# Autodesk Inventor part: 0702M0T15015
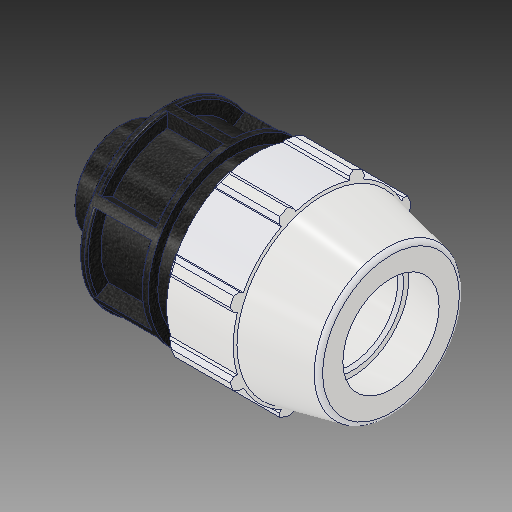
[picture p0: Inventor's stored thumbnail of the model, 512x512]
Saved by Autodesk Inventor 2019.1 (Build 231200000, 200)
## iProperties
Created: 2017-02
Part Number: 0702M0T15015
Material: PVC-Piping
Description: PLASSON MALE ADAPTOR 1 1/2'' - 1 1/2''M
Document SubType Name: Modeling
Designer: KIM
Mass: 92.6774 g
Surface Area: 199.44 cm^2
Volume: 66.1981 cm^3
Density: 1.4 g/cm^3
Appearance: PTFE
Author: KIM
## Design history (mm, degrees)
derived "0702M0T.ipt"
feature "Solid1::0702M0T.ipt"
tag "TaggingFeature1"
body "Solid1"
other parameters: "d2" = 48.1, "d4" = 19.26771, "d5" = 33.7185, "d7" = 96.012, "d8" = 72.009, "d9" = 19.26771, "d11" = 3.85354, "d12" = 76.8096, "d13" = 120 deg, "d14" = 72.15, "d15" = 12 deg, "d16" = 86.4108, "d18" = 2.405, "d19" = 35 deg, "d20" = 17.5 deg, "d21" = 89.29116, "d23" = 0, "d25" = 360 deg, "d27" = 1.92024, "d34" = 4.8006, "d36" = 0, "d42" = 33.7185, "d43" = 2.88036, "d46" = 1.443, "d51" = 134.874, "d52" = 22.098, "d53" = 0.962, "d55" = 360 deg, "d57" = 47.803, "d58" = 33.4621, "d59" = 26.9748, "d61" = 27.178, "d_" = 48.1, "E_" = 96.012, "H_" = 134.874, "l_" = 106.934, "l_2" = 22.098, "G_" = 47.803
